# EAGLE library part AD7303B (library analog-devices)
+2.7 V to +5.5 V, Serial Input, Dual Voltage Output 8-Bit DAC Source: http://www.analog.com/UploadedFiles/Data_Sheets/AD7303.pdf
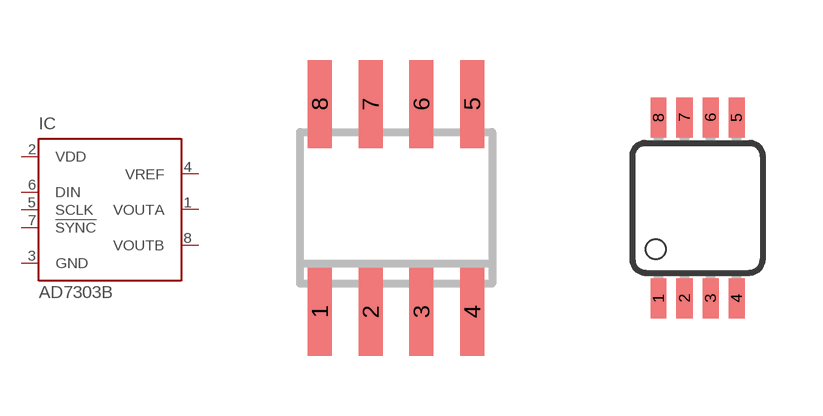
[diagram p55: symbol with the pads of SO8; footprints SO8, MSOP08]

Designator prefix IC

## AD7303BR (MPN: AD7303BRZ; OC_FARNELL: 1838896; OC_NEWARK: 19M8835)  [SO8]
1  VOUTA  out
2  VDD  pwr
3  GND  pwr
4  VREF  pas
5  SCLK  in
6  DIN  in
7  !SYNC  in
8  VOUTB  out

## AD7303BRM (MF: ALTERA CORPORATION; MPN: AD7303BRMZ; OC_FARNELL: 1464525; OC_NEWARK: 59K4694)  [MSOP08]
Pads as for SO8

## AD7303BN (MPN: AD7303BNZ; OC_FARNELL: 1079413; OC_NEWARK: 19M0854)  [DIL08]
Pads as for SO8

## Footprint SO8 (pad centres in mm)
8-Lead Small Outline IC (SO-8) Source: http://www.analog.com/UploadedFiles/Data_Sheets/703465986AD8611_2_0.pdf
smd 0.6 x 2.2: 1 -1.905,-2.6; 2 -0.635,-2.6; 3 0.635,-2.6; 4 1.905,-2.6; 5 1.905,2.6; 6 0.635,2.6; 7 -0.635,2.6; 8 -1.905,2.6

## Footprint MSOP08 (pad centres in mm)
8-Lead micro SO (RM-8) Source: http://www.analog.com/UploadedFiles/Data_Sheets/703465986AD8611_2_0.pdf
smd 0.4 x 1: 1 -0.976,-2.263; 2 -0.326,-2.263; 3 0.324,-2.263; 4 0.974,-2.263; 5 0.974,2.262; 6 0.324,2.262; 7 -0.326,2.262; 8 -0.976,2.262

## Footprint DIL08 (pad centres in mm)
Dual In Line Package
drill 0.813 long: 1 -3.81,-3.81; 2 -1.27,-3.81; 3 1.27,-3.81; 4 3.81,-3.81; 5 3.81,3.81; 6 1.27,3.81; 7 -1.27,3.81; 8 -3.81,3.81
